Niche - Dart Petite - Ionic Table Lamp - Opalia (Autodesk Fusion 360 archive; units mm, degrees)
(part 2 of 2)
derived_base_feature "Derived Base Feature" bodies "E26 Base"
named bodies: "E26 Base"

design "Chinois"
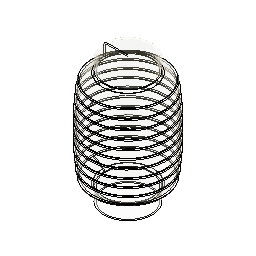
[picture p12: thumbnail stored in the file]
named bodies: "Chinois"

design "2-Pole Plug End"
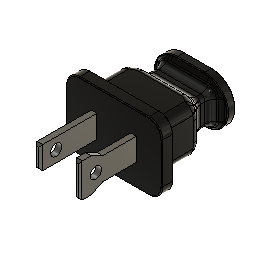
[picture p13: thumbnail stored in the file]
sketch "Sketch1" plane through (0, 0, 0) normal (0, 1, 0) x axis (1, 0, 0)
  line L1 (9.6837, 9.525) -> (-9.6837, 9.525)
  line L2 (13.4938, -5.715) -> (13.4938, 5.715)
  line L3 (-9.6837, -9.525) -> (9.6837, -9.525)
  line L4 (-13.4937, 5.715) -> (-13.4937, -5.715)
  line L5 (13.4938, -9.525) -> (-13.4937, 9.525)
  line L6 (-13.4937, -9.525) -> (13.4938, 9.525)
  arc A1 centre (-9.6837, -5.715) radius 3.81 clockwise from (-9.6837, -9.525) to (-13.4937, -5.715)
  arc A2 centre (9.6837, -5.715) radius 3.81 clockwise from (13.4938, -5.715) to (9.6837, -9.525)
  arc A3 centre (9.6837, 5.715) radius 3.81 clockwise from (9.6837, 9.525) to (13.4938, 5.715)
  arc A4 centre (-9.6837, 5.715) radius 3.81 clockwise from (-13.4937, 5.715) to (-9.6837, 9.525)
  point P6 (0, 0)
  point P1 (0, 0)
  point P5 (-13.4937, -9.525)
  point P4 (13.4938, -9.525)
  point P3 (13.4938, 9.525)
  point P2 (-13.4937, 9.525)
  horizontal L1
  perpendicular L1 L2
  parallel L1 L3
  parallel L2 L4
  coincident L5 P6
  coincident L6 P6
  coincident P1 P6
  coincident P5 L4
  coincident P5 L3
  tangent L4 A1
  tangent L3 A1
  coincident P4 L3
  coincident P4 L2
  tangent L3 A2
  tangent L2 A2
  equal A1 A2
  coincident P3 L2
  coincident P3 L1
  tangent L2 A3
  tangent L1 A3
  equal A1 A3
  coincident P2 L1
  coincident P2 L4
  tangent L1 A4
  tangent L4 A4
  equal A1 A4
  dimension "d1" distance P4 P5 = 26.9875
  dimension "d2" distance P2 P5 = 19.05
  dimension "d3" radius A1 = 3.81
extrude "Extrude1" new body sketch "Sketch1" profile of L1 L2 L3 L4 A1 A2 A3 A4 along normal blind 3.175
sketch "Sketch2" plane through (0, 3.175, 0) normal (0, 1, 0) x axis (-1, 0, 0)
  line L1 (9.6837, -9.525) -> (-9.6837, -9.525)
  line L2 (13.4937, 5.715) -> (13.4937, -5.715)
  line L3 (-9.6837, 9.525) -> (9.6837, 9.525)
  line L4 (-13.4938, -5.715) -> (-13.4938, 5.715)
  line L5 (10.16, -6.35) -> (-10.16, -6.35)
  line L6 (10.16, 6.35) -> (10.16, -6.35)
  line L7 (-10.16, 6.35) -> (10.16, 6.35)
  line L8 (-10.16, -6.35) -> (-10.16, 6.35)
  line L9 (10.16, 6.35) -> (-10.16, -6.35)
  line L10 (-10.16, 6.35) -> (10.16, -6.35)
  arc A1 centre (-9.6837, -5.715) radius 3.81 clockwise from (-9.6837, -9.525) to (-13.4938, -5.715)
  arc A2 centre (9.6837, -5.715) radius 3.81 clockwise from (13.4937, -5.715) to (9.6837, -9.525)
  arc A3 centre (9.6837, 5.715) radius 3.81 clockwise from (9.6837, 9.525) to (13.4937, 5.715)
  arc A4 centre (-9.6837, 5.715) radius 3.81 clockwise from (-13.4938, 5.715) to (-9.6837, 9.525)
  point P18 (0, 0)
  point P1 (0, 0)
  horizontal L5
  perpendicular L5 L6
  parallel L5 L7
  parallel L6 L8
  coincident L9 P18
  coincident L10 P18
  coincident P1 P18
extrude "Extrude2" add sketch "Sketch2" profile of L5 L6 L7 L8 along normal blind 9.525
sketch "Sketch3" plane through (0, 12.7, 0) normal (0, 1, 0) x axis (-1, 0, 0)
  line L1 (-10.16, -6.35) -> (-10.16, 6.35)
  line L2 (10.16, -6.35) -> (-10.16, -6.35)
  line L3 (10.16, 6.35) -> (10.16, -6.35)
  line L4 (-10.16, 6.35) -> (10.16, 6.35)
  line L5 (-7.1437, 3.9688) -> (7.1437, 3.9688)
  line L6 (-7.1437, -3.9688) -> (-7.1437, 3.9688)
  line L7 (7.1437, -3.9688) -> (-7.1437, -3.9688)
  line L8 (7.1437, 3.9688) -> (7.1437, -3.9688)
  line L9 (-7.1437, -3.9688) -> (7.1437, 3.9688)
  line L10 (7.1437, -3.9688) -> (-7.1437, 3.9688)
  point P10 (0, 0)
  point P1 (0, 0)
  point P8 (-7.1437, -3.9688)
  point P9 (7.1437, -3.9688)
  point P7 (-7.1437, 3.9688)
  horizontal L5
  perpendicular L5 L6
  parallel L5 L7
  parallel L6 L8
  coincident L9 P10
  coincident L10 P10
  coincident P1 P10
  dimension "d8" distance P8 P9 = 14.2875
  dimension "d9" distance P7 P8 = 7.9375
extrude "Extrude3" add sketch "Sketch3" profile of L5 L6 L7 L8 along normal blind 11.1125
fillet "Fillet1" radius 2.286 1.27 0.254
chamfer "Chamfer1" distance 3.429
fillet "Fillet2" radius 2.54 1.905
sketch "Sketch4" plane through (0, 23.8125, 0) normal (0, 1, 0) x axis (-1, 0, 0)
  line L1 (-7.1437, -2.6987) -> (-7.1437, 2.6987)
  line L2 (5.8737, -3.9688) -> (-5.8737, -3.9688)
  line L3 (7.1437, 2.6987) -> (7.1437, -2.6987)
  line L4 (-5.8737, 3.9688) -> (5.8737, 3.9688)
  line L5 (-3.81, 6.604) -> (3.81, 6.604)
  line L6 (3.81, -6.604) -> (-3.81, -6.604)
  line L7 (-10.414, 0) -> (10.414, 0)
  arc A1 centre (-5.8737, 2.6987) radius 1.27 clockwise from (-7.1437, 2.6987) to (-5.8737, 3.9688)
  arc A2 centre (-5.8737, -2.6987) radius 1.27 clockwise from (-5.8737, -3.9688) to (-7.1437, -2.6987)
  arc A3 centre (5.8737, -2.6987) radius 1.27 clockwise from (7.1437, -2.6987) to (5.8737, -3.9688)
  arc A4 centre (5.8737, 2.6987) radius 1.27 clockwise from (5.8737, 3.9688) to (7.1437, 2.6987)
  arc A5 centre (-3.81, 0) radius 6.604 clockwise from (-3.81, -6.604) to (-3.81, 6.604)
  arc A6 centre (3.81, 0) radius 6.604 clockwise from (3.81, 6.604) to (3.81, -6.604)
  point P20 (10.414, 0)
  point P21 (-10.414, 0)
  tangent L5 A5
  tangent A5 L6
  parallel L5 L6
  tangent L6 A6
  tangent L5 A6
  midpoint A6 P20
  midpoint A5 P21
  perpendicular L1 L7
extrude "Extrude4" add sketch "Sketch4" profile of A1 L1 A2 L2 A3 L3 A4 L4 L5 A5 L6 A6 against normal blind 2.286
chamfer "Chamfer2" distance 1.778
fillet "Fillet3" radius 1.778
fillet "Fillet4" radius 0.254
fillet "Fillet5" radius 0.254
fillet "Fillet6" radius 0.254
fillet "Fillet7" radius 3.175
sketch "Sketch5" plane through (0, 0, 0) normal (0, -1, 0) x axis (1, 0, 0)
  line L1 (-13.2397, -5.715) -> (-13.2397, 5.715)
  line L2 (9.6837, -9.271) -> (-9.6837, -9.271)
  line L3 (13.2397, 5.715) -> (13.2397, -5.715)
  line L4 (-9.6837, 9.271) -> (9.6837, 9.271)
  line L5 (-6.35, -3.175) -> (-6.35, 3.175)
  line L6 (6.35, 3.175) -> (-6.35, -3.175)
  line L7 (-6.35, 3.175) -> (6.35, -3.175)
  line L8 (-4.7625, 3.175) -> (-6.35, 3.175)
  line L9 (-4.7625, -3.175) -> (-4.7625, 3.175)
  line L10 (-6.35, -3.175) -> (-4.7625, -3.175)
  line L11 (-6.35, 3.175) -> (-6.35, -3.175)
  line L12 (0, -3.302) -> (0, 3.81)
  line L13 (4.7625, -3.175) -> (4.7625, 3.175)
  line L14 (4.7625, 3.175) -> (6.35, 3.175)
  line L15 (6.35, -3.175) -> (6.35, 3.175)
  line L16 (6.35, -3.175) -> (4.7625, -3.175)
  arc A1 centre (-9.6837, 5.715) radius 3.556 clockwise from (-13.2397, 5.715) to (-9.6837, 9.271)
  arc A2 centre (-9.6837, -5.715) radius 3.556 clockwise from (-9.6837, -9.271) to (-13.2397, -5.715)
  arc A3 centre (9.6837, -5.715) radius 3.556 clockwise from (13.2397, -5.715) to (9.6837, -9.271)
  arc A4 centre (9.6837, 5.715) radius 3.556 clockwise from (9.6837, 9.271) to (13.2397, 5.715)
  point P18 (0, 0)
  point P1 (0, 0)
  point P14 (-6.35, -3.175)
  point P27 (6.35, -3.175)
  point P17 (-6.35, 3.175)
  point P26 (6.35, 3.175)
  point P19 (-4.7625, 3.175)
  point P24 (4.7625, 3.175)
  point P20 (-4.7625, -3.175)
  point P25 (4.7625, -3.175)
  point P21 (-6.35, -3.175)
  point P28 (6.35, -3.175)
  point P15 (6.35, -3.175)
  point P16 (6.35, 3.175)
  coincident L6 P18
  coincident L7 P18
  coincident P1 P18
  horizontal L8
  vertical L9
  horizontal L10
  vertical L11
  vertical L12
  symmetric P14 L12 P27
  symmetric P17 L12 P26
  symmetric P19 L12 P24
  symmetric P20 L12 P25
  symmetric P21 L12 P28
  dimension "d36" distance P15 P16 = 6.35
  dimension "d37" distance P17 P19 = 1.5875
extrude "Extrude5" add sketch "Sketch5" profile of L5 L8 L9 L10 L11 L13 L14 L15 L16 along normal blind 15.875
sketch "Sketch7" plane through (0, 0, 3.175) normal (0, 0, 1) x axis (-1, 0, 0)
  line L1 (-4.7625, 0) -> (-6.35, 0)
  line L2 (-4.7625, 15.875) -> (-4.7625, 0)
  line L3 (-6.35, 15.875) -> (-4.7625, 15.875)
  line L4 (-6.35, 0) -> (-6.35, 15.875)
  line L5 (-4.7625, 15.875) -> (-6.35, 15.875)
  line L6 (-4.7625, 9.525) -> (-4.7625, 15.875)
  line L7 (-6.35, 9.525) -> (-4.7625, 9.525)
  line L8 (-6.35, 15.875) -> (-6.35, 9.525)
  point P5 (-6.35, 15.875)
  point P6 (-6.35, 15.875)
  point P9 (-6.35, 9.525)
  horizontal L5
  vertical L6
  horizontal L7
  vertical L8
  coincident P5 P6
  dimension "d45" distance P6 P9 = 6.35
extrude "Extrude7" add sketch "Sketch7" profile of L2 L3 L4 L5 L6 L7 L8 against normal blind 7.9375 and along normal blind 1.5875
chamfer "Chamfer3" distance 0.508
chamfer "Chamfer4" distance 0.635 distance 0.635
sketch "Sketch6" plane through (6.35, 0, 0) normal (1, 0, 0) x axis (0, 1, 0)
  line L1 (0, -3.175) -> (-9.525, -3.175)
  line L2 (0, 3.175) -> (0, -3.175)
  line L3 (-9.525, 3.175) -> (0, 3.175)
  line L4 (-15.367, -4.6355) -> (-15.367, 4.6355)
  line L5 (-11.43, 0) -> (-16.002, 0)
  line L6 (-9.525, -4.7625) -> (-15.24, -4.7625)
  line L7 (-9.525, -3.175) -> (-9.525, -4.7625)
  line L8 (-9.525, 4.7625) -> (-9.525, 3.175)
  line L9 (-15.24, 4.7625) -> (-9.525, 4.7625)
  line L10 (-15.24, -4.7625) -> (-15.367, -4.6355)
  line L11 (-15.367, 4.6355) -> (-15.24, 4.7625)
  circle C1 centre (-11.43, 0) radius 1.5875
  point P9 (-11.43, 0)
  point P10 (-11.43, 0)
  perpendicular L4 L5
  coincident P9 P10
  dimension "d42" diameter C1 = 3.175
extrude "Extrude6" cut sketch "Sketch6" profile of C1 against normal blind 20.32
chamfer "Chamfer5" distance 3.175 distance 1.5875 distance 3.175 distance 1.5875
component_from_bodies "Body->Comp"
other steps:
base_feature "Base Feature" bodies "2-Pole Plug End"
create_component "CreateComponent1"
remove_body "RemoveBody1"
named bodies: "2-Pole Plug End"

design "Marble Base - Plastic Insert"
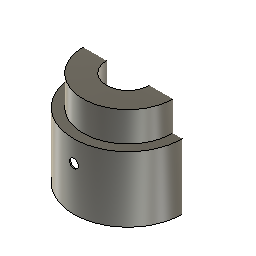
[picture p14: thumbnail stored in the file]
sketch "Sketch1" plane through (0, 0, 0) normal (0, 0, 1) x axis (1, 0, 0)
  circle C1 centre (0, 0) radius 50.038
  point P1 (0, 0)
  point P2 (0, 0)
  coincident P1 P2
  dimension "d1" diameter C1 = 100.076
extrude "Extrude1" new body sketch "Sketch1" along normal blind 72.898 bodies "Plastic Insert"
shell "Shell1" innerThickness 1.016
work_plane "WorkPlane1" AlongDistance 18.034
sketch "Sketch2" plane through (0, 0, 90.932) normal (0, 0, 1) x axis (1, 0, 0)
  circle C1 centre (0, 0) radius 20.701
  point P1 (0, 0)
  point P2 (0, 0)
  coincident P1 P2
  dimension "d6" diameter C1 = 41.402
extrude "Extrude2" add sketch "Sketch2" against normal blind 65.024
shell "Shell2" innerThickness 1.016
sketch "Sketch3" plane through (0, 0, 0) normal (0, 1, 0) x axis (1, 0, 0)
  line L1 (5.08, -20.32) -> (-5.08, -20.32)
  line L2 (5.08, 20.32) -> (5.08, -20.32)
  line L3 (-5.08, 20.32) -> (5.08, 20.32)
  line L4 (-5.08, -20.32) -> (-5.08, 20.32)
  line L5 (5.08, 20.32) -> (-5.08, -20.32)
  line L6 (-5.08, 20.32) -> (5.08, -20.32)
  point P6 (0, 0)
  point P1 (0, 0)
  horizontal L1
  perpendicular L1 L2
  parallel L1 L3
  parallel L2 L4
  coincident L5 P6
  coincident L6 P6
  coincident P1 P6
extrude "Extrude3" cut sketch "Sketch3" profile of L1 L2 L3 L4 along normal blind 91.44
sketch "Sketch4" plane through (0, 0, 0) normal (0, 1, 0) x axis (1, 0, 0)
  line L1 (0, -40.64) -> (0, 0)
  circle C1 centre (0, -40.64) radius 4.064
  point P1 (0, 0)
  point P2 (0, 0)
  point P3 (0, -40.64)
  point P4 (0, -40.64)
  coincident P1 P2
  vertical L1
  coincident P3 P4
  dimension "d12" diameter C1 = 8.128
work_plane "WorkPlane2" AlongDistance -91.44
sketch "Sketch5" plane through (0, -91.44, 0) normal (0, 1, 0) x axis (1, 0, 0)
  circle C1 centre (0, -40.64) radius 4.064
extrude "Extrude4" cut sketch "Sketch5" along normal blind 63.5
sketch "Sketch6" plane through (0, 0, 26.924) normal (0, 0, 1) x axis (-1, 0, 0)
  circle C1 centre (0, 0) radius 19.685
  circle C2 centre (0, 0) radius 5.461
  concentric C1 C2
  dimension "d16" diameter C2 = 10.922
extrude "Extrude5" cut sketch "Sketch6" profile of C2 against normal blind 15.24
sketch "Sketch7" plane through (0, 0, 72.898) normal (0, 0, 1) x axis (-1, 0, 0)
  circle C1 centre (0, 0) radius 20.701
  circle C2 centre (0, 0) radius 50.038
  circle C3 centre (0, 0) radius 20.701
  circle C4 centre (0, 0) radius 45.72
  point P1 (0, 0)
  point P3 (0, 0)
  point P4 (0, 0)
  coincident P1 P3
  coincident P1 P4
extrude "Extrude6" add sketch "Sketch7" profile of C1 C3 C4 along normal blind 18.034
sketch "Sketch8" plane through (0, 0, 71.882) normal (0, 0, -1) x axis (1, 0, 0)
  circle C1 centre (0, 0) radius 20.701
  circle C2 centre (0, 0) radius 49.022
  circle C3 centre (0, 0) radius 20.701
  circle C4 centre (0, 0) radius 44.704
  point P1 (0, 0)
  point P3 (0, 0)
  point P4 (0, 0)
  coincident P1 P3
  coincident P1 P4
  dimension "d21" diameter C4 = 89.408
extrude "Extrude7" cut sketch "Sketch8" profile of C1 C3 C4 against normal blind 17.78
extrude "Extrude8" add of existing geometry blind 9.398
extrude "Extrude9" cut of existing geometry blind -9.398
component_from_bodies "Body->Comp"
offset_faces "OffsetFaces1" distance 4.445
offset_faces "OffsetFaces2" distance -4.445
offset_faces "OffsetFaces3" distance 3.175
offset_faces "OffsetFaces4" distance 3.175
offset_faces "OffsetFaces5" distance 3.175
offset_faces "OffsetFaces6" distance -3.175
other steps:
base_feature "Base Feature" bodies "Plastic Insert"
create_component "CreateComponent1"
remove_body "RemoveBody1"
named bodies: "Plastic Insert"

design "Rubber Grommet"
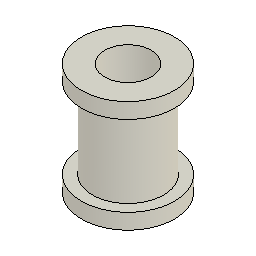
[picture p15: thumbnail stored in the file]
sketch "Sketch1" plane through (0, 0, 0) normal (0, 1, 0) x axis (1, 0, 0)
  line L1 (0, 3.048) -> (0, -12.7)
  line L2 (5.842, 0.508) -> (5.842, -12.7)
  line L3 (3.81, 3.048) -> (3.81, -15.24)
  line L4 (7.62, -12.7) -> (7.62, -15.24)
  line L5 (7.62, 3.048) -> (7.62, 0.508)
  line L6 (7.62, 0.508) -> (5.842, 0.508)
  line L7 (7.62, -12.7) -> (5.842, -12.7)
  line L8 (7.62, -15.24) -> (3.81, -15.24)
  line L9 (7.62, 3.048) -> (3.81, 3.048)
  vertical L1
  collinear L4 L5
revolve "Revolve1" sketch "Sketch1" AlongAngle 360 bodies "Rubber Grommet"
component_from_bodies "Body->Comp"
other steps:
base_feature "Base Feature" bodies "Rubber Grommet"
create_component "CreateComponent1"
remove_body "RemoveBody1"
named bodies: "Rubber Grommet"

design "Trove - TL"
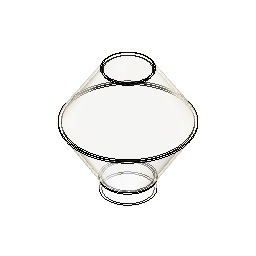
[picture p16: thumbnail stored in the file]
derived_base_feature "Derived Base Feature" bodies "Trove"
hole "Hole1" HoleDepth 88.9 HoleDiameter 44.45 TipAngle 118
sketch "Sketch1" plane through (0, 0, 0) normal (1, 0, 0) x axis (0, 1, 0)
  line L1 (0, 243.0601) -> (0, 247.8226)
  line L2 (-50.8, -12.7122) -> (-50.8, 10.9447)
  line L3 (0, -25.4) -> (0, 243.0601)
  line L4 (-46.0375, -12.7122) -> (-50.8, -12.7122)
  line L5 (-46.0375, -12.7122) -> (-46.0375, 12.3043)
  line L6 (-45.9716, 247.8226) -> (0, 247.8226)
  line L7 (-43.3841, 243.0601) -> (0, 243.0601)
  line L8 (-122.8321, 128.6352) -> (-51.757, 14.2971)
  line L9 (-117.1907, 128.5808) -> (-46.9945, 15.6567)
  line L10 (-48.6353, 246.3754) -> (-122.7993, 132.0392)
  line L11 (-46.0478, 241.6129) -> (-117.1579, 131.9848)
  arc A1 centre (-57.15, 10.9447) radius 6.35 clockwise from (-51.757, 14.2971) to (-50.8, 10.9447)
  arc A2 centre (-52.3875, 12.3043) radius 6.35 clockwise from (-46.9945, 15.6567) to (-46.0375, 12.3043)
  arc A3 centre (-114.4942, 130.257) radius 3.175 between (-117.1579, 131.9848) and (-117.1907, 128.5808)
  arc A4 centre (-120.1356, 130.3114) radius 3.175 between (-122.7993, 132.0392) and (-122.8321, 128.6352)
  arc A5 centre (-45.9716, 244.6476) radius 3.175 between (-45.9716, 247.8226) and (-48.6353, 246.3754)
  arc A6 centre (-43.3841, 239.8851) radius 3.175 clockwise from (-46.0478, 241.6129) to (-43.3841, 243.0601)
  point P3 (0, 247.8226)
  point P4 (0, 243.0601)
  vertical L1
  vertical L3
  tangent L5 A2
  perpendicular L1 L6
  perpendicular L1 L7
  tangent L11 A3
  tangent L9 A3
  tangent L10 A4
  tangent L8 A4
  equal A3 A4
  tangent L6 A5
  tangent L10 A5
  tangent L11 A6
  tangent L7 A6
  dimension "d8" distance P3 P4 = 4.7625
  dimension "d11" radius A2 = 6.35
  dimension "d15" radius A3 = 3.175
  dimension "d16" radius A5 = 3.175
  dimension "d17" radius A6 = 3.175
revolve "Revolve1" sketch "Sketch1" AlongAngle 180 bodies "Trove - TL"
revolve "Revolve2" sketch "Sketch1" AlongAngle -180
component_from_bodies "Body->Comp"
remove_body "RemoveBody2"
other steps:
base_feature "Base Feature" bodies "Trove - TL"
create_component "CreateComponent1"
remove_body "RemoveBody1"
named bodies: "Trove", "Trove - TL"

design "T9-5In"
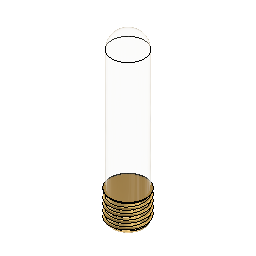
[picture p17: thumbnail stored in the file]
sketch "Sketch1" plane through (0, 0, 0) normal (0, 1, 0) x axis (1, 0, 0)
  line L1 (0, 0) -> (0, -127)
  line L2 (12.7, -127) -> (-12.7, -127)
  line L3 (12.7, -12.7) -> (12.7, -127)
  line L4 (-12.7, -127) -> (-12.7, -12.7)
  arc A1 centre (0, -12.7) radius 12.7 clockwise from (-12.7, -12.7) to (12.7, -12.7)
  point P1 (0, 0)
  point P3 (0, 0)
  coincident P1 P3
  vertical L1
  horizontal L2
  vertical L3
  vertical L4
revolve "Revolve1" sketch "Sketch1" AlongAngle 360 bodies "BU-T10-5-LED-120V"
derived_base_feature "Derived Base Feature" bodies "E26 Base"
move "Move1"
component_from_bodies "Body->Comp"
copy_paste "CutPaste"
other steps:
base_feature "Base Feature" bodies "BU-T10-5-LED-120V"
create_component "CreateComponent1"
create_component "CreateComponent2"
remove_body "RemoveBody1"
remove_instance "RemoveInstance1"
named bodies: "BU-T10-5-LED-120V", "E26 Base"

design "Orb 8.5In - Solitaire Petite"
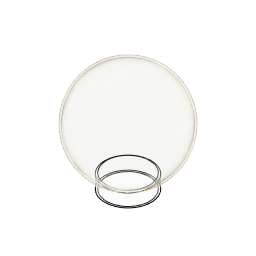
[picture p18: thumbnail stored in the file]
sketch "Sketch1" plane through (0, 0, 0) normal (0, 1, 0) x axis (1, 0, 0)
  line L1 (0, 190.5) -> (0, -127)
  line L2 (50.8, 190.5) -> (50.8, -127)
  line L3 (-50.8, 190.5) -> (-50.8, -127)
  line L4 (50.8, 95.25) -> (-50.8, 95.25)
  line L5 (50.8, 123.825) -> (-50.8, 123.825)
  line L6 (101.6, -107.95) -> (0, -107.95)
  circle C1 centre (0, 0) radius 107.95
  point P1 (0, 0)
  point P2 (0, 0)
  point P5 (50.8, -127)
  point P7 (-50.8, -127)
  point P6 (50.8, 190.5)
  point P8 (-50.8, 190.5)
  point P9 (-50.8, 95.25)
  point P10 (50.8, 95.25)
  point P13 (0, -107.95)
  coincident P1 P2
  vertical L1
  symmetric L1 P5 P7
  symmetric L1 P6 P8
  coincident C1 P9
  coincident L3 P9
  coincident C1 P10
  coincident L2 P10
  perpendicular L2 L4
  coincident C1 P13
  coincident L1 P13
  tangent C1 L6
  dimension "d1" diameter C1 = 215.9
  dimension "d2" = 50.8
  dimension "d4" = -28.575
revolve "Revolve1" sketch "Sketch1" AlongAngle 360 bodies "Orb-8.5"
shell "Shell1" innerThickness 3.81
component_from_bodies "Body->Comp"
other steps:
base_feature "Base Feature" bodies "Orb-8.5"
create_component "CreateComponent1"
remove_body "RemoveBody1"
named bodies: "Orb-8.5"

design "Dart"
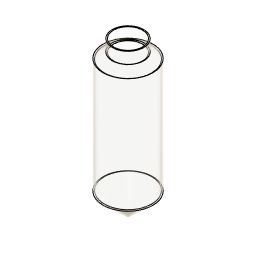
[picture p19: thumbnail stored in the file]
sketch "Sketch1" plane through (0, 0, 0) normal (0, 0, 1) x axis (1, 0, 0)
work_plane "WorkPlane1" AlongDistance 76.2
sketch "Sketch2" plane through (0, 0, 76.2) normal (0, 0, 1) x axis (1, 0, 0)
sketch "Sketch3" plane through (0, 0, 76.2) normal (0, 0, 1) x axis (1, 0, 0)
sketch "Sketch4" plane through (0, 0, 76.2) normal (0, 0, 1) x axis (1, 0, 0)
  circle C1 centre (0, 0) radius 82.55
  point P1 (0, 0)
  point P2 (0, 0)
  coincident P1 P2
  dimension "d2" diameter C1 = 165.1
loft "Loft1" sketch "Sketch4" bodies "Dart Grand"
extrude "Extrude1" add of existing geometry blind 381
work_plane "WorkPlane2" AlongDistance 19.05
sketch "Sketch5" plane through (0, 0, 476.25) normal (0, 0, 1) x axis (1, 0, 0)
  circle C1 centre (0, 0) radius 52.07
  point P1 (0, 0)
  point P2 (0, 0)
  coincident P1 P2
  dimension "d6" diameter C1 = 104.14
loft "Loft2" sketch "Sketch5"
extrude "Extrude2" add of existing geometry blind 38.1
shell "Shell3" innerThickness 3.81
component_from_bodies "Body->Comp"
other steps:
base_feature "Base Feature" bodies "Dart Grand"
create_component "CreateComponent1"
remove_body "RemoveBody1"
named bodies: "Dart Grand"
